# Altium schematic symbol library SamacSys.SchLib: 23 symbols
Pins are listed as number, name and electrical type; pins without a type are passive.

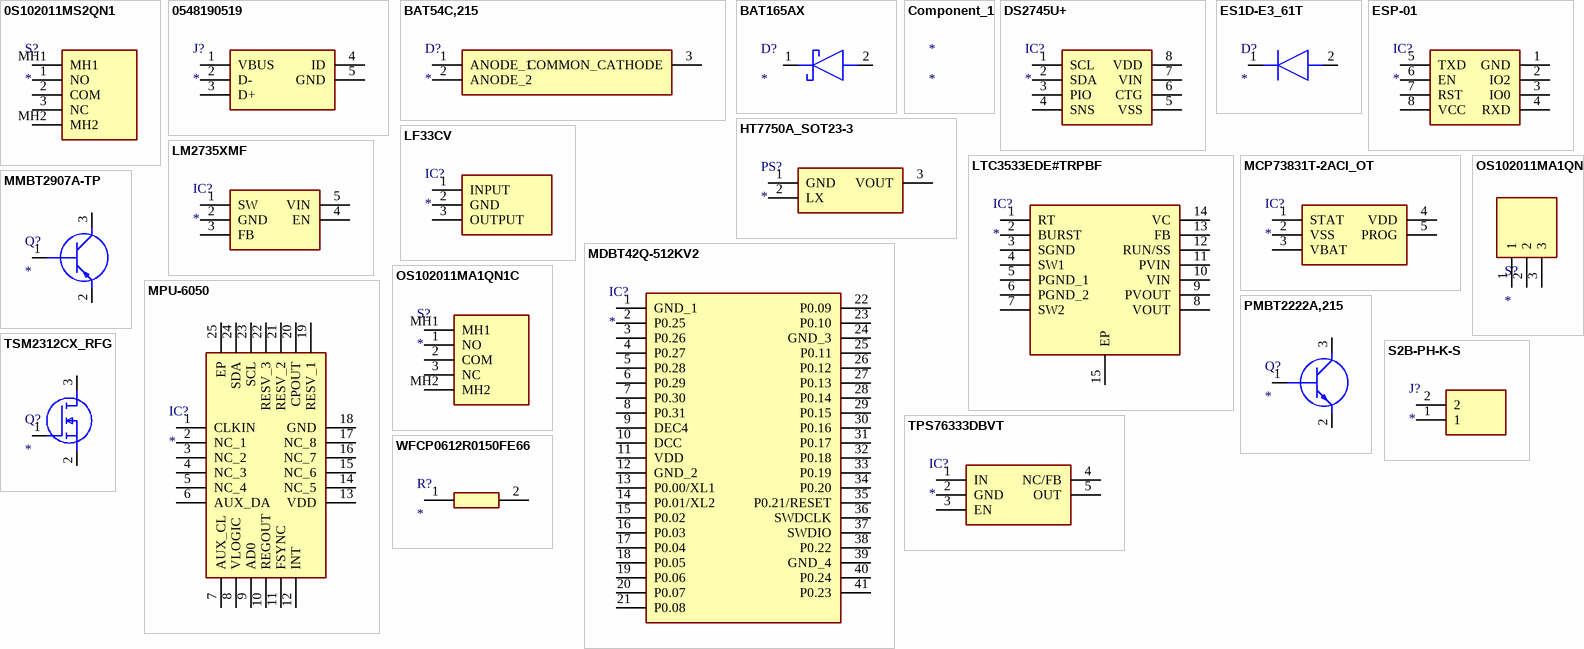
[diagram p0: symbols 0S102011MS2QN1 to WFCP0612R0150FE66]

## 0S102011MS2QN1
designator S?
Switch; Manufacturer_Name: C & K COMPONENTS; Manufacturer_Part_Number: 0S102011MS2QN1; Description: Slide Switches
footprint 0S102011MS2QN1
pins: 1 NO, 2 COM, 3 NC, MH1, MH2

## 0548190519
designator J?
Connector; Manufacturer_Name: Molex; Manufacturer_Part_Number: 0548190519
footprint 0548190519
pins: 1 VBUS, 2 D-, 3 D+, 4 ID, 5 GND

## BAT54C,215
designator D?
Schottky Diode; Manufacturer_Name: Nexperia; Manufacturer_Part_Number: BAT54C,215
footprint BAT54C215
pins: 1 ANODE_1, 2 ANODE_2, 3 COMMON_CATHODE

## BAT165AX
designator D?
Schottky Diode; Manufacturer_Name: Nexperia; Manufacturer_Part_Number: BAT165AX
footprint BAT165AX
pins: 1 K, 2 A

## Component_1
designator *

## DS2745U+
designator IC?
Integrated Circuit; Manufacturer_Name: Maxim Integrated; Manufacturer_Part_Number: DS2745U+
footprint SOP65P490X110-8N
pins: 1 SCL, 2 SDA, 3 PIO, 4 SNS, 5 VSS, 6 CTG, 7 VIN, 8 VDD

## ES1D-E3_61T
designator D?
Diode; Manufacturer_Name: Vishay; Manufacturer_Part_Number: ES1D-E3/61T
footprint DIOM5127X229N
pins: 1 K, 2 A

## ESP-01
designator IC?
Integrated Circuit; Manufacturer_Name: Ai-Thinker; Manufacturer_Part_Number: ESP-01
footprint ESP01
pins: 1 GND, 2 IO2, 3 IO0, 4 RXD, 5 TXD, 6 EN, 7 RST, 8 VCC

## HT7750A_SOT23-3
designator PS?
Power Supply; Manufacturer_Name: Holtek; Manufacturer_Part_Number: HT7750A SOT23-3
footprint SOT95P190X145-3N
pins: 1 GND, 2 LX, 3 VOUT

## LF33CV
designator IC?
Integrated Circuit; Manufacturer_Name: STMicroelectronics; Manufacturer_Part_Number: LF33CV
footprint TO255P460X1020X2008-3P
pins: 1 INPUT, 2 GND, 3 OUTPUT

## LM2735XMF
designator IC?
Integrated Circuit; Manufacturer_Name: Texas Instruments; Manufacturer_Part_Number: LM2735XMF
footprint SOT95P285X110-5N
pins: 1 SW, 2 GND, 3 FB, 4 EN, 5 VIN

## LTC3533EDE#TRPBF
designator IC?
Integrated Circuit; Manufacturer_Name: Analog Devices; Manufacturer_Part_Number: LTC3533EDE#TRPBF
footprint SON50P300X400X80-15N-D
pins: 1 RT, 2 BURST, 3 SGND, 4 SW1, 5 PGND_1, 6 PGND_2, 7 SW2, 8 VOUT, 9 PVOUT, 10 VIN, 11 PVIN, 12 RUN/SS, 13 FB, 14 VC, 15 EP

## MCP73831T-2ACI_OT
designator IC?
Integrated Circuit; Manufacturer_Name: Microchip; Manufacturer_Part_Number: MCP73831T-2ACI/OT
footprint SOT95P270X145-5N
pins: 1 STAT, 2 VSS, 3 VBAT, 4 VDD, 5 PROG

## MDBT42Q-512KV2
designator IC?
Integrated Circuit; Manufacturer_Name: Raytac; Manufacturer_Part_Number: MDBT42Q-512KV2
footprint MDBT42Q512KV2
pins: 1 GND_1, 2 P0.25, 3 P0.26, 4 P0.27, 5 P0.28, 6 P0.29, 7 P0.30, 8 P0.31, 9 DEC4, 10 DCC, 11 VDD, 12 GND_2, 13 P0.00/XL1, 14 P0.01/XL2, 15 P0.02, 16 P0.03, 17 P0.04, 18 P0.05, 19 P0.06, 20 P0.07, 21 P0.08, 22 P0.09, 23 P0.10, 24 GND_3, 25 P0.11, 26 P0.12, 27 P0.13, 28 P0.14, 29 P0.15, 30 P0.16, 31 P0.17, 32 P0.18, 33 P0.19, 34 P0.20, 35 P0.21/RESET, 36 SWDCLK, 37 SWDIO, 38 P0.22, 39 GND_4, 40 P0.24, 41 P0.23

## MMBT2907A-TP
designator Q?
Transistor BJT PNP; Manufacturer_Name: Micro Commercial Components (MCC); Manufacturer_Part_Number: MMBT2907A-TP
footprint SOT96P237X112-3N
pins: 1 B, 2 E, 3 C

## MPU-6050
designator IC?
Integrated Circuit; Manufacturer_Name: TDK
footprint MPU6050
pins: 1 CLKIN, 2 NC_1, 3 NC_2, 4 NC_3, 5 NC_4, 6 AUX_DA, 7 AUX_CL, 8 VLOGIC, 9 AD0, 10 REGOUT, 11 FSYNC, 12 INT, 13 VDD, 14 NC_5, 15 NC_6, 16 NC_7, 17 NC_8, 18 GND, 19 RESV_1, 20 CPOUT, 21 RESV_2, 22 RESV_3, 23 SCL, 24 SDA, 25 EP

## OS102011MA1QN1
designator S?
Switch; Manufacturer_Name: C & K COMPONENTS; Manufacturer_Part_Number: OS102011MA1QN1
footprint OS102011MA1QN1
pins: 1, 2, 3

## OS102011MA1QN1C
designator S?
Switch; Manufacturer_Name: C & K COMPONENTS; Manufacturer_Part_Number: OS102011MA1QN1C
footprint OS102011MA1QN1C
pins: 1 NO, 2 COM, 3 NC, MH1, MH2

## PMBT2222A,215
designator Q?
Transistor BJT NPN; Manufacturer_Name: Nexperia; Manufacturer_Part_Number: PMBT2222A,215
footprint PMBT2222A215
pins: 1 B, 2 E, 3 C

## S2B-PH-K-S
designator J?
Connector; Manufacturer_Name: JST (JAPAN SOLDERLESS TERMINALS); Manufacturer_Part_Number: S2B-PH-K-S
footprint S2BPHKS
pins: 1, 2

## TPS76333DBVT
designator IC?
Integrated Circuit; Manufacturer_Name: Texas Instruments; Manufacturer_Part_Number: TPS76333DBVT
footprint SOT95P280X145-5N
pins: 1 IN, 2 GND, 3 EN, 4 NC/FB, 5 OUT

## TSM2312CX_RFG
designator Q?
MOSFET (N-Channel); Manufacturer_Name: Taiwan Semiconductor; Manufacturer_Part_Number: TSM2312CX RFG
footprint SOT95P280X130-3N
pins: 1 G, 2 S, 3 D

## WFCP0612R0150FE66
designator R?
Resistor; Manufacturer_Name: Vishay; Manufacturer_Part_Number: WFCP0612R0150FE66
footprint RESC1632X80N
pins: 1, 2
